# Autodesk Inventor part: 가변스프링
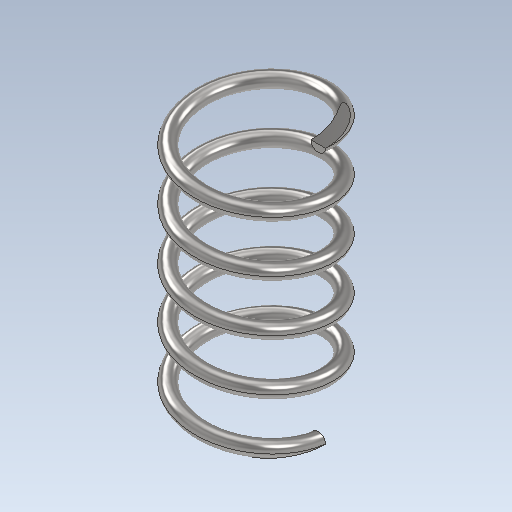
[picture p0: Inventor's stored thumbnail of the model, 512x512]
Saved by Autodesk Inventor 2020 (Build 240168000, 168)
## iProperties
Created: 2023-11
Part Number: 가변스프링
Material: 강철, 탄소
Document SubType Name: Modeling
Designer: oem
Density: 7.85 g/cm^3
Appearance: 반연마
Mass: 6.50574 g
Surface Area: 16.8157 cm^2
Volume: 0.828757 cm^3
Author: oem
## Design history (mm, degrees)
sketch "스케치1"
  geometry: L1 (0, 0)-(8.5, 0); L2 (8.5, 0)-(8.5, 35); L3 (8.5, 35)-(0, 35); L4 (0, 35)-(0, 0); C1 r 1 at (8.5, 0)
  constraints: 8 end point, 2 parallel, 1 centre point, 1 coincident, 1 horizontal, 1 perpendicular
  dimensions: "d0" = 17 diameter of L2 L4; "d1" = 35 distance of L1.end L2.end (derived); "d2" = 2 diameter of C1
feature "코일1" sketch "스케치1" pitch "d3" = 10; turns "d5" = 5; dims "d4" = 35 (= d1), "d6" = 0, angle "d7" = 90 deg, angle "d8" = 90 deg, "d9" = 0, "d10" = 0
sketch "스케치2"
  geometry: L1 (-7.5, 0)-(-9.5, 0) reference; 1 further point
  constraints: 1 horizontal alignment
extrude "돌출1" cut sketch "스케치2" extent not by distance; stored distance "d11" = 33.412; taper "d12" = 0 deg
node "작업 평면1"
sketch "스케치3"
  geometry: L1 (-1, 0)-(1, 0) reference; 1 further point
  constraints: 1 horizontal alignment
extrude "돌출2" cut sketch "스케치3" extent not by distance; stored distance "d14" = 0.565; taper "d15" = 0 deg
node "솔리드1"
node "절단 모서리 투영1"
node "절단 모서리 투영2"
other parameters: "d13" = 90 deg
